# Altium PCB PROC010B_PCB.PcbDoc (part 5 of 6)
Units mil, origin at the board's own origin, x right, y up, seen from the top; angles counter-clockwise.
Board outline 3180 x 2565 mil, 6 copper layers (TOP, L2, L3, L4, L5, BOTTOM), stack 55.54 mil thick; 362 components, 264 nets, 1248 pads, 1144 vias.
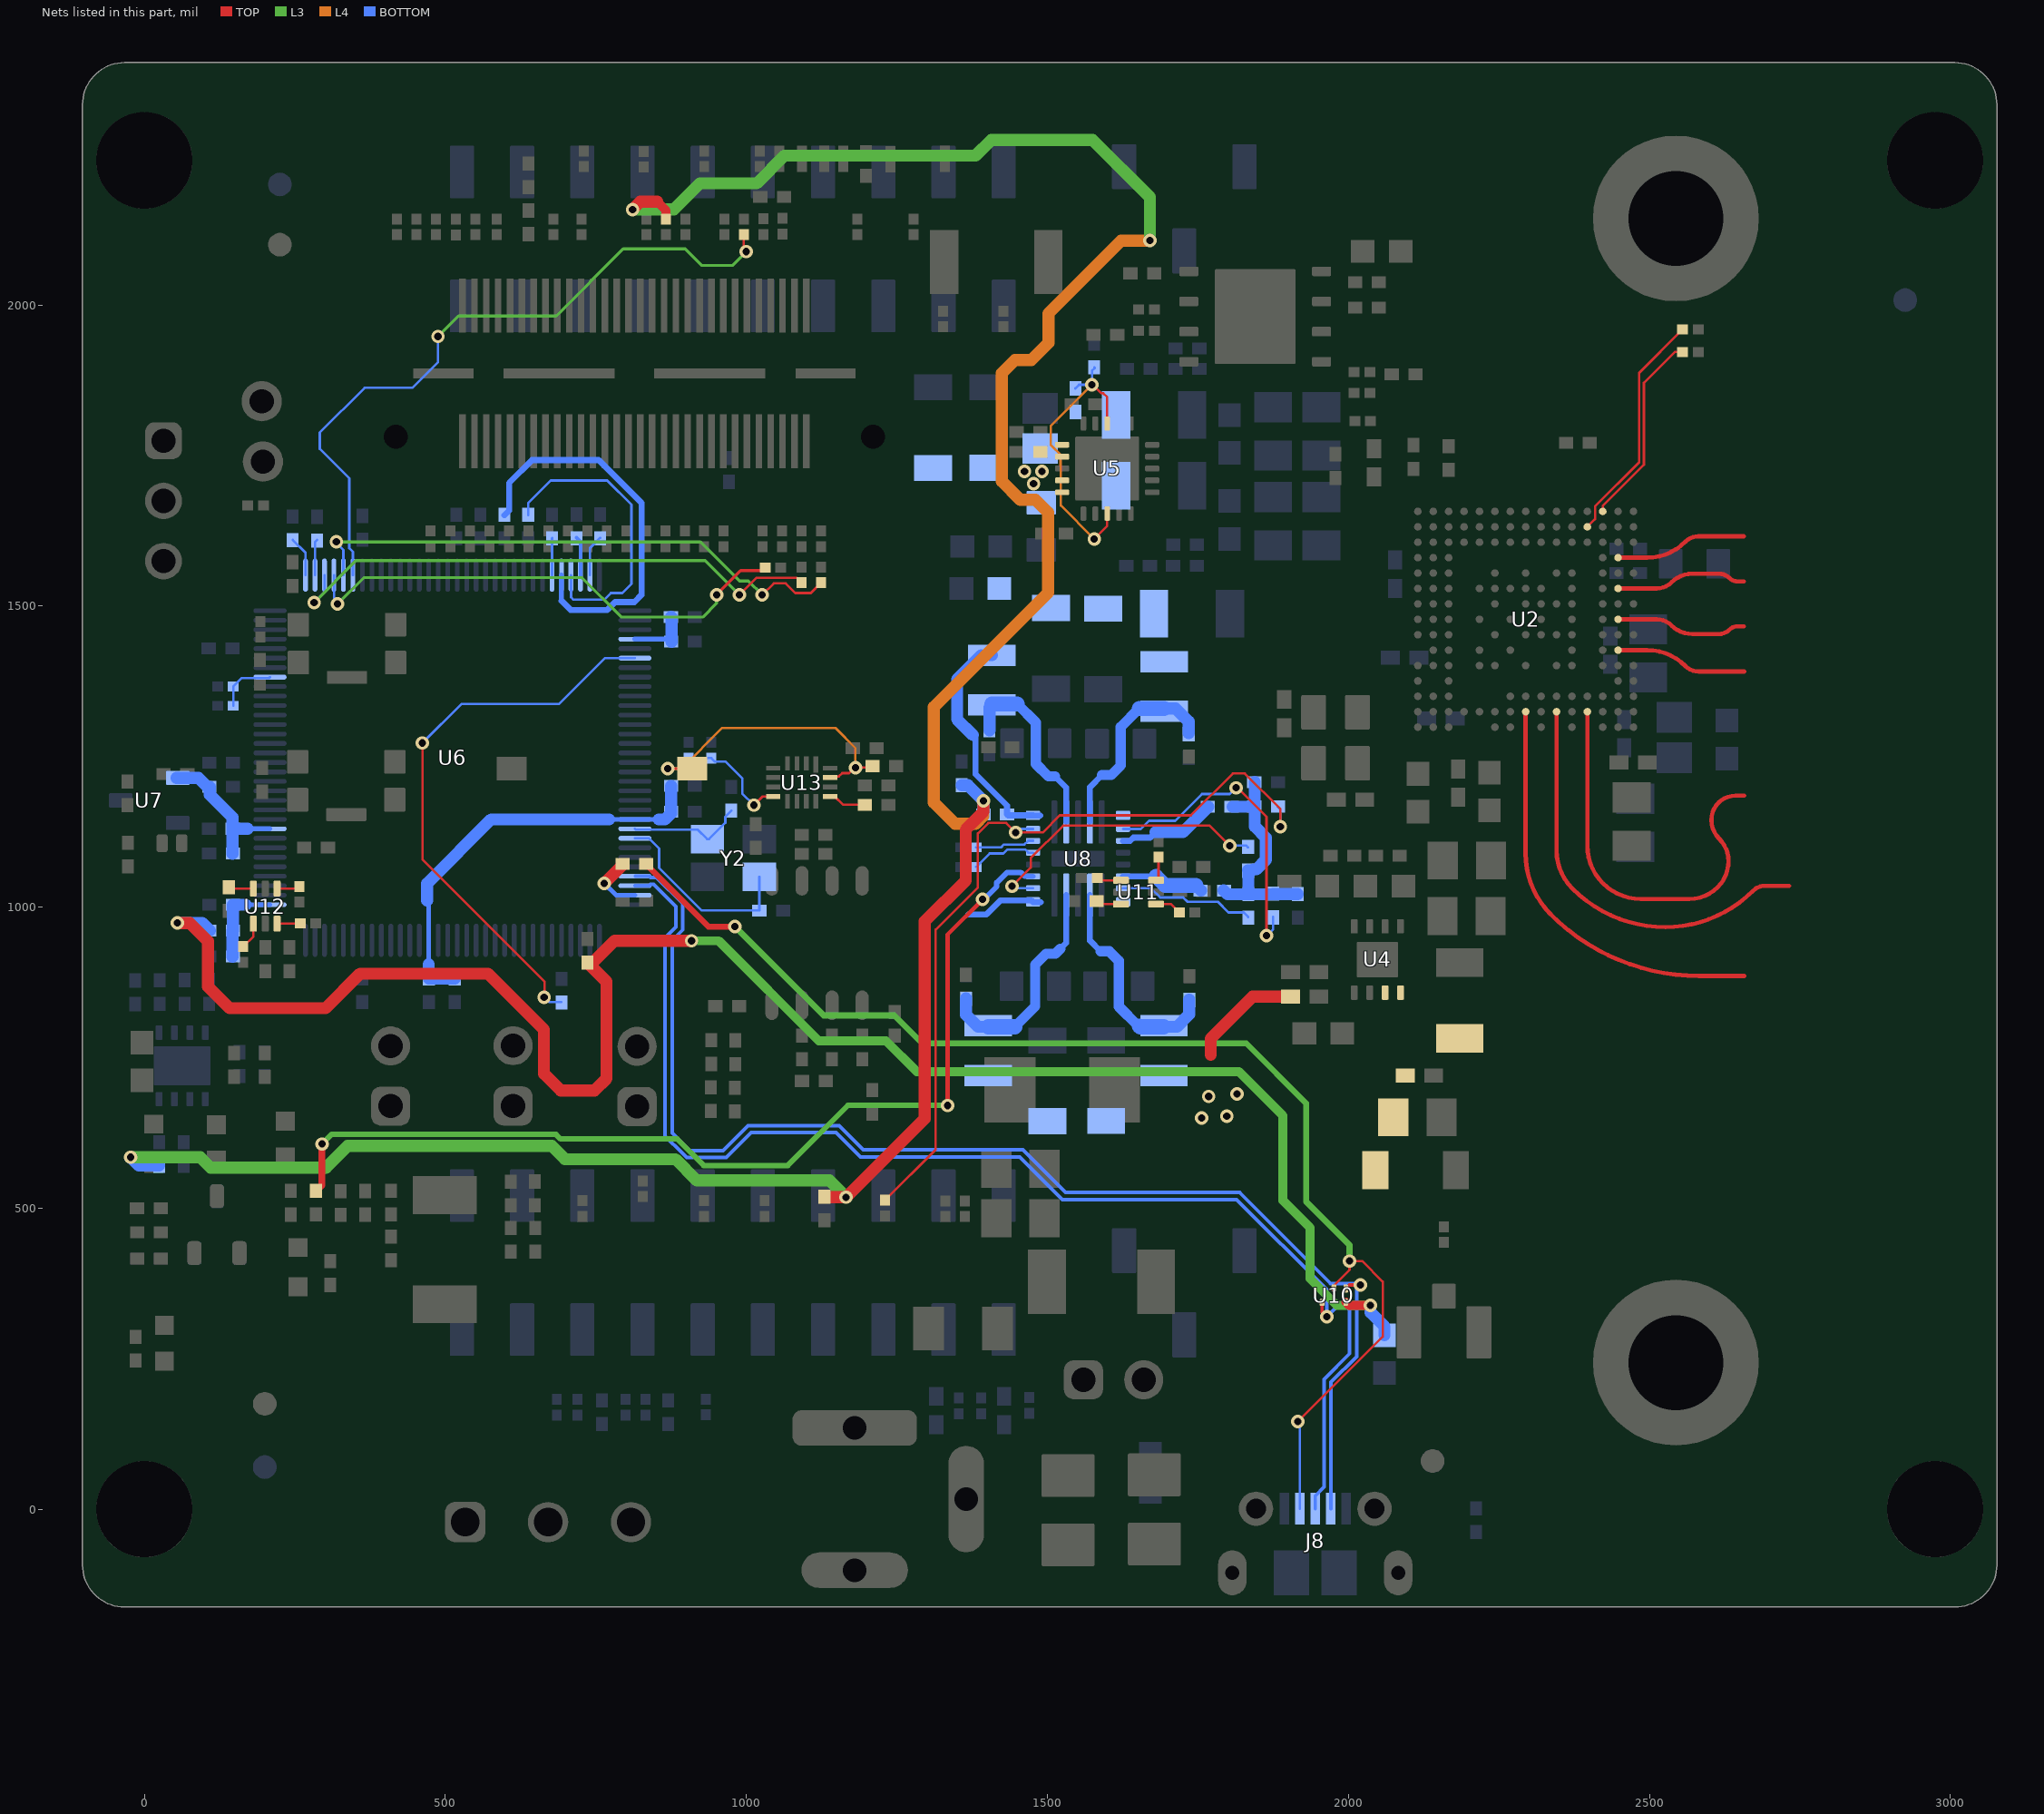
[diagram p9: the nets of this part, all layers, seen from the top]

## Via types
v1: diameter 22.4, hole 12.2, TOP to BOTTOM, tented both sides, 621 vias
v2: diameter 13.77/15.74 (per signal layer), hole 5.9, TOP to L2, tented top, 508 vias
v3: diameter 19.68, hole 7.87, TOP to BOTTOM, tented top, 7 vias
v4: diameter 19.68, hole 7.87, TOP to BOTTOM, 4 vias
v5: diameter 19.68, hole 7.87, TOP to BOTTOM, tented both sides, 3 vias
v6: diameter 19.68, hole 7.87, TOP to BOTTOM, tented bottom, 1 vias

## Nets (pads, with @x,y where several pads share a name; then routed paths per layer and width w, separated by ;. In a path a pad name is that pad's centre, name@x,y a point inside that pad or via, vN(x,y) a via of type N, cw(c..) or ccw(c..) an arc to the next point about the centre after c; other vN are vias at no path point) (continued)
NetR123_1: R123.1 U6.63 | length 69.2
  BOTTOM w4: U6.63@740.14,1551.19 740.14,1596.11 R123.1@757.28,1613.25
NetR124_1: R124.1 U6.61 | length 504.9
  BOTTOM w4: R124.1@637.72,1650.75 637.72,1671.22 675.02,1708.52 768.8,1708.52 809,1668.32 809,1536.5 794,1521.5 775,1521.5 764,1510.5 713,1510.5 709,1514.5 709,1550.83 U6.61@708.64,1551.19
NetR125_1: R125.1 S1.2 U13.15 | length 504.1
  TOP w4: v1(869.19,1230) S1.2@910,1230 ; U13.15@1139.1,1215.08 1140.97,1216.96 1153.7,1216.96 1159.2,1222.46 1170.65,1222.46 v1@1179.8,1231.61 ; v1(1181.07,1231.61) 1207.07,1231.61 R125.1@1209.58,1234.12
  L4 w4: v1(869.19,1230) 892.6,1230 960.04,1297.45 1147.8,1297.45 1181.07,1264.17 v1(1181.07,1231.61)
NetR126_1: R126.1 U6.62 | length 64.8
  BOTTOM w6: R126.1@717.68,1613.25 724.39,1606.54 U6.62@724.39,1551.19
NetR127_1: R127.1 U6.60 | length 666.9
  BOTTOM w8: 692.89,1508.61 U6.60@692.89,1551.19
  BOTTOM w10: R127.1@598.12,1650.75 606,1658.63 606,1704.43 643.95,1742.38 754.73,1742.38 825.8,1671.31 825.8,1518.3 814,1506.5 782,1506.5 769,1493.5 708,1493.5 692.89,1508.61
NetR128_2: R128.2 U6.33 | length 67.5
  BOTTOM w4: R128.2@246.5,1609.95 267.7,1588.75 U6.33@267.7,1551.19
NetR129_2: R129.2 U6.34 | length 59.9
  BOTTOM w4: U6.34@283.44,1551.19 283.44,1606.04 R129.2@287,1609.6
NetR143_1: R143.1 U8.16 | length 165
  BOTTOM w10: U8.16@1625.81,1110.02 1637.53,1110.03 1643,1115.5 1671,1115.5 1679.82,1124.32
  BOTTOM w20: 1679.82,1124.32 1725.27,1124.32 R143.1@1767.45,1166.5
NetR144_2: R144.2 U8.5 | length 108.5
  BOTTOM w4: R144.2@1381.77,1066.69 1404.08,1089 1427,1089 1433.49,1095.49 1462.92,1095.49 1468.07,1090.34 U8.5@1476.2,1090.34
NetR146_1: R146.1 U8.6 | length 98.9
  BOTTOM w4: R146.1@1381.77,1099.19 1423.19,1099.19 1427.83,1103.83 1461.94,1103.83 1468.13,1110.03 U8.6@1476.2,1110.02
NetR147_1: R147.1 U8.19 | length 139
  BOTTOM w10: U8.19@1625.81,1050.97 1680.53,1050.97
  BOTTOM w20: R147.1@1746.6,1036 R147.1@1755.1,1027.5
  BOTTOM w25: 1680.53,1050.97 1695.5,1036 R147.1@1746.6,1036
NetR152_1: R152.1 U6.95 | length 104
  TOP w20: v1(764,1039.5) 795.1,1070.6 R152.1@795.1,1071.5
  BOTTOM w8: v1(764,1039.5) 783.81,1019.69 U6.95@814.94,1019.69
NetR179_1: R179.1 U11.3 | length 43.1
  TOP w4: R179.1@1581.25,1009.92 1586.11,1005.06 U11.3@1622.33,1005.07
NetR180_2: R180.2 U11.1 | length 41.2
  TOP w4: R180.2@1582.77,1048.33 1586.66,1044.44 U11.1@1622.33,1044.44
NetR181_1: R181.1 U11.4 | length 44.4
  TOP w4: U11.4@1680.59,1005.07 1705.34,1005.06 R181.1@1719.23,991.17
NetR182_1: R182.1 U11.6 | length 40
  TOP w4: U11.6@1680.59,1044.44 1684.67,1048.52 R182.1@1684.67,1082.79
NetR184_1: R184.1 U12.3 | length 41.4
  TOP w4: R184.1@140.38,1032.25 141.96,1030.67 U12.3@181.13,1030.67
NetR185_2: R185.2 U12.1 | length 38.8
  TOP w4: U12.1@220.5,1030.67 254.29,1030.67 R185.2@257.83,1034.21
NetR186_1: R186.1 U12.6 | length 38.7
  TOP w4: U12.6@220.5,972.4 257.87,972.41 R186.1@258.79,973.33
NetR188_2: R188.2 U12.4 | length 45.4
  TOP w4: R188.2@163.83,934.21 181.12,951.5 U12.4@181.13,972.4
NetR194_2: R194.2 U6.59 | length 61.9
  BOTTOM w4: U6.59@677.14,1551.19 677.14,1612.57 R194.2@677.52,1612.95
NetR195_1: R195.1 U13.13 | length 63.2
  TOP w4: U13.13@1139.1,1183.59 1146.9,1183.59 1160.68,1169.81 R195.1@1196.58,1169.81
NetR197_2: R197.2 U2.P4 | length 393.5
  TOP w4: U2.P4@2396.91,1631.44 2409.75,1644.28 2409.75,1665.25 2483,1738.5 2483,1887.2 2555.01,1959.21 R197.2@2555.01,1959
NetR198_2: R198.2 U2.R3 | length 327.3
  TOP w4: U2.R3@2422.5,1657.03 2422.5,1666 2491,1734.5 2491,1870.64 2542.36,1922 R198.2@2555.01,1922
PGOOD: R27.1 R107.2 R138.2 R141.2 R159.1 | length 4589.2
  TOP w15: 852.15,2171.36 866.61,2156.9 R27.1@866.61,2142.71
  TOP w20: v1(811,2158.5) 823.86,2171.36 852.15,2171.36 ; R107.2@1129.75,518.18 v1(1165.78,518.18) 1296.38,648.78 1296.38,976.2 1364.54,1044.36 1364.54,1129.13 1393.72,1158.31 v1(1393.72,1176.67)
  L3 w20: v1(-23,584.5) 93.04,584.5 110.2,567.34 301.89,567.34 337.84,603.3 676.71,603.3 698.74,581.28 882.26,581.28 917.54,546 1137.96,546 v1(1165.78,518.18) ; v1(811,2158.5) 879.46,2158.5 922.83,2201.86 1017.13,2201.86 1063.27,2248 1381,2248 1407,2274 1575.14,2274 1670.34,2178.8 v1(1670.34,2106.77)
  L4 w20: v1(1393.72,1176.67) 1393.72,1150.96 1381.05,1138.3 1346.64,1138.3 1311.35,1173.59 1311.35,1332.35 1501.24,1522.24 1501.24,1655.5 1480.29,1676.45 1454.85,1676.45 1424.36,1706.93 1424.36,1886.63 1446.28,1908.55 1473.25,1908.55 1501.76,1937.06 1501.76,1985.85 1622.68,2106.77 v1(1670.34,2106.77)
  BOTTOM w20: v1(-23,584.5) -9.31,570.81 R159.1@24.43,570.81 ; R138.2@1357.78,1202.28 1368.11,1202.28 v1(1393.72,1176.67) R141.2@1393.72,1154.01
PMIC_1V0: C30.2 C31.2 C32.2 C40.2 C81.2 L4.2 L5.1 L8.1 R46.1 R120.2 U5.1 U5.2 U5.4 U5.5 U8.1 | length 130.9
  BOTTOM w10: 1368.72,987.88 1398.93,987.88 1422.37,1011.32 1473.53,1011.32 U8.1@1476.2,1008.65 ; U8.1@1476.2,1007.88 1488.82,1007.88
  other v1: 1477.07,1703.31 1461.98,1723.32 1491.25,1723.21
PMIC_1V2: C54.2 L1.2 L9.1 U8.14
PMIC_1V8: C21.1 C23.1 C25.1 C82.2 L3.2 L7.1 R84.2 U4.7 U4.8 U8.21 | length 188.3
  TOP w20: 1771.28,754.5 1771.28,781.5 1841,851.22 R84.2@1903.73,851.22
  other v1: 1756,649.5 1798,652.5 1768,685.5 1815,689.5
PMIC_CLK: R97.2 U8.3 | length 1666.1
  TOP w7.08: v1(1334.3,670.49) 1334.3,954.63 v1(1392.53,1012.86)
  TOP w11: R97.2@285,528.05 295,538.05 v1(295,606.5)
  L3 w9: v1(295,606.5) 310.78,622.28 683.9,622.28 691.42,614.75 885.25,614.75 929.05,570.95 1068.95,570.95 1168.49,670.49 v1(1334.3,670.49)
  BOTTOM w9: v1(1392.53,1012.86) 1394.86,1012.86 1416,1034 1416,1040.48 1433.11,1057.59 1455.85,1057.59 1462.47,1050.97 U8.3@1476.2,1050.97
PMIC_EN1: R102.2 R142.1 U8.7 | length 1350.2
  TOP w4: R102.2@1230.25,513.27 1314.37,597.39 1314.37,962.49 1384.59,1032.71 1384.59,1122.31 1401.99,1139.71 1431.79,1139.71 v1(1447.5,1124) 1492.41,1124 1520.75,1152.33 1738.33,1152.33 1808,1222 1828,1222 1887,1163 v1(1887,1133.5)
  BOTTOM w4: v1(1447.5,1124) 1453.21,1129.71 U8.7@1476.2,1129.71 ; R142.1@1882.25,1167.04 1887,1162.29 v1(1887,1133.5)
PMIC_EN2: R148.1 U8.15 | length 520.5
  TOP w4: v1(1813.65,1198) 1816,1198 1864,1150 v1(1864,952.5)
  BOTTOM w4: U8.15@1625.81,1129.71 1655.21,1129.71 1668.82,1143.32 1712.32,1143.32 1756.81,1187.81 1802.78,1187.81 1813.65,1198.69 v1(1813.65,1198) ; v1(1864,952.5) 1875,963.5 R148.1@1875,983.6
PMIC_EN3: R145.1 U8.2 | length 494.2
  TOP w4: v1(1441.5,1034.5) 1472.48,1065.48 1472.48,1081.57 1526.25,1135.33 1769.67,1135.33 v1(1803,1102)
  BOTTOM w4: v1(1441.5,1034.5) 1444.71,1031.29 U8.2@1476.2,1031.28 ; v1(1803,1102) 1830.49,1102 R145.1@1833.44,1099.05
PMIC_NRST: R150.2 U8.20 | length 227.8
  BOTTOM w4: U8.20@1625.81,1031.28 1672.21,1031.29 1687.5,1016 1725.5,1016 1732.5,1009 1782.99,1009 1800.99,991 1825.99,991 R150.2@1833.74,983.25
PMICOUT_3V3: C55.2 L2.2 R133.1 R141.1 U8.8 | length 388.9
  BOTTOM w10: 1376.47,1285.53 1380.65,1281.35 1380.65,1220.85 1433.09,1168.41 R141.1@1433.09,1154.01 1434.74,1152.35 U8.8@1476.2,1152.35 ; U8.8@1476.2,1152.15 1488.2,1152.15
  BOTTOM w20: 1376.47,1285.53 1350,1312 1350,1378.33 1389.91,1418.24 L2.2@1407.85,1418.24
PMICVIO_3V3: R139.2 R142.2 R143.2 R145.2 R147.2 R148.2 R149.1 R150.1 | length 376.5
  BOTTOM w20: R147.2@1792.9,1027.5 1799.35,1021.05 R150.1@1833.74,1021.05 ; R143.2@1807.91,1166.5 R142.2@1844.45,1167.04 ; R139.2@1844.45,1207.54 R142.2@1844.45,1167.04 ; R149.1@1916.14,1021.05 1915.79,1021.4 1875,1021.4 1874.65,1021.05 R150.1@1833.74,1021.05 ; R150.1@1833.74,1021.05 1833.74,1060.95 1833.44,1061.25 1840.75,1061.25 1842,1062.5 1847,1062.5 1863,1078.5 1863,1115 1844.45,1133.55 R142.2@1844.45,1167.04
RX1: U2.M2 | length 218.6
  TOP w7.08: U2.M2@2448.09,1580.26 2496.4,1580.26 ccw(c2496.4,1669.28) 2559.79,1606.78 cw(c2581.07,1585.5) 2581.07,1615.6 2657.22,1615.6
RX2: U2.K2 | length 218.8
  TOP w7.08: U2.K2@2448.09,1529.08 2512.28,1529.08 ccw(c2512.28,1563.6) 2536.69,1539.19 cw(c2571.24,1504.66) 2571.24,1553.5 2615.82,1553.5 cw(c2615.82,1528.95) 2633.18,1546.31 ccw(c2646.47,1559.58) 2646.47,1540.8 2656.92,1540.8
RX3: U2.H2 | length 218.8
  TOP w7.08: U2.H2@2448.09,1477.9 2512.28,1477.9 cw(c2512.28,1443.38) 2536.69,1467.79 ccw(c2571.24,1502.32) 2571.24,1453.48 2615.82,1453.48 ccw(c2615.82,1478.03) 2633.18,1460.67 ; 2633.19,1460.68 cw(c2646.47,1447.4) 2646.47,1466.18 2656.92,1466.18
RX4: U2.F2 | length 218.9
  TOP w7.08: U2.F2@2448.09,1426.72 2496.4,1426.72 cw(c2496.4,1337.7) 2559.79,1400.2 ccw(c2581.5,1421.91) 2581.5,1391.2 2657.4,1391.2
SPICLK1: R75.1 R76.1 U13.8 | length 193.5
  TOP w4: v1(1012.58,1169.33) 1026.83,1183.59 U13.8@1044.61,1183.59
  BOTTOM w4: R75.1@904.07,1247.48 R76.1@941.93,1247.48 947.94,1241.48 965.54,1241.48 993.15,1213.86 993.15,1188.75 v1(1012.58,1169.33)
SS_CTRL: R119.2 R120.1 U5.8 U5.18 | length 504.4
  TOP w4: v1(1574.07,1867.4) 1575.74,1867.4 1589.91,1853.24 1592.9,1853.24 1599.35,1846.8 U5.18@1599.35,1803.12 ; v1(1577.96,1611.47) 1599.35,1632.86 U5.8@1599.35,1653.52
  L4 w4: v1(1574.07,1867.4) 1505.5,1798.83 1505.5,1767.57 1521.82,1751.25 1521.82,1731.91 1522.36,1731.91 1522.36,1667.08 v1(1577.96,1611.47)
  BOTTOM w4: R120.1@1546.63,1861.48 1552.56,1867.4 v1(1574.07,1867.4) 1574.07,1890.75 1578.87,1895.55 R119.2@1577.96,1896.45
SW0: L2.1 R190.2 U8.10 | length 322.3
  BOTTOM w10: 1512.51,1217 1531.31,1198.2 U8.10@1531.32,1141.13
  BOTTOM w17: 1449.82,1337.53 1480.85,1306.5 1480.85,1237.8 1501.65,1217 1512.51,1217
  BOTTOM w20: R190.2@1403.85,1293.43 1403.85,1331.56 L2.1@1407.85,1335.56
  BOTTOM w25: L2.1@1407.85,1337.53 1449.82,1337.53
SW1: L1.1 R191.2 U8.12 | length 342.4
  BOTTOM w10: U8.12@1570.69,1141.13 1570.69,1199.24 1590.95,1219.5
  BOTTOM w17: 1590.95,1219.5 1606.05,1219.5 1621.95,1235.4 1621.95,1299.23 1652.68,1329.96
  BOTTOM w20: L1.1@1694.05,1329.96 1713.07,1329.96 1734.8,1308.23 R191.2@1734.8,1288.55
  BOTTOM w25: 1652.68,1329.96 L1.1@1694.05,1329.96
SW2: L4.1 R192.2 U8.25 | length 379.6
  BOTTOM w10: 1521.55,930.8 1531.31,940.56 U8.25@1531.32,1019.87
  BOTTOM w17: 1445.92,801.17 1479.85,835.1 1479.85,904.34 1498.01,922.5 1513.25,922.5 1521.55,930.8
  BOTTOM w20: R192.2@1364.9,848.45 1364.9,821.17 1384.9,801.17 L4.1@1401.55,801.17
  BOTTOM w25: L4.1@1401.55,801.17 1445.92,801.17
SW3: L3.1 R193.2 U8.23 | length 377.5
  BOTTOM w10: U8.23@1570.69,1019.87 1570.69,944.32 1588.51,926.5
  BOTTOM w17: 1588.51,926.5 1602.85,926.5 1618.65,910.7 1618.65,834.7 1650.84,802.51 1652.68,802.51
  BOTTOM w20: L3.1@1693.55,801.17 1714.99,801.17 1735.6,821.78 R193.2@1735.6,846.45
  BOTTOM w25: 1652.68,802.51 1654.02,801.17 L3.1@1693.55,801.17
TX1: U2.B4 | length 696.2
  TOP w7.08: U2.B4@2396.91,1324.36 2396.91,1102.05 ccw(c2485.46,1102.05) 2485.46,1013.5 2566.65,1013.5 ccw(c2566.65,1079.79) 2613.53,1032.92 ; 2613.54,1032.93 ccw(c2570.24,1076.22) 2631.47,1076.22 ccw(c2578.8,1076.22) 2616.05,1113.46 cw(c2647.37,1144.78) 2603.07,1144.78 cw(c2643.55,1144.8) 2614.93,1173.43 cw(c2642.62,1145.76) 2642.61,1184.9 2657.3,1184.9
TX2: U2.B6 | length 696.2
  TOP w7.08: U2.B6@2345.73,1324.36 2345.73,1094.33 ccw(c2435.71,1094.33) 2372.08,1030.71 ccw(c2526.5,1185.06) 2526.5,966.73 ccw(c2526.5,1172.53) 2672,1026.99 cw(c2692.07,1006.94) 2692.06,1035.3 2732.11,1035.3
TX3: U2.B8 | length 696.3
  TOP w7.08: U2.B8@2294.55,1324.36 2294.34,1324.15 2294.34,1089.06 ccw(c2437.96,1089.06) 2336.4,987.51 ccw(c2582.22,1233.3) 2582.22,885.68 2657.3,885.68
VBUS_1_DETECT: C69.2 R151.1 R153.2 U6.1 | length 147.8
  BOTTOM w8: 168.55,1003.95 U6.1@208.64,1003.95
  BOTTOM w20: R153.2@146.55,917.74 146.55,961.04 146.95,961.44 146.95,1003.56 147.34,1003.95 168.55,1003.95
VDDC_1: C62.2 C64.2 C74.2 C75.2 U6.87 U6.115 | length 701
  BOTTOM w8: 469.65,1010.85 472.42,1008.08 472.42,905.08 ; 771.82,1145.68 854.18,1145.68
  BOTTOM w20: 469.65,1010.85 469.65,1039.15 576.18,1145.68 771.82,1145.68 ; 472.42,905.08 472.42,881.71 472.68,881.45 C74.2@515.6,881.45 ; 854.18,1145.68 865,1145.68 874.96,1155.64 C64.2@874.96,1158.3 C62.2@874.96,1201.2
XDSET_1_D_N: J8.2 U6.93 U10.1 | length 2188.8
  TOP w6: U10.1@1995.68,366.33 2001.88,372.52 v1(2019.99,372.52)
  BOTTOM w6: U6.93@815.54,1051.19 838.99,1051.19 840.8,1049.38 850.87,1049.38 894.6,1005.65 894.6,962.25 876.6,944.24 876.6,624.75 905.6,595.75 905.6,595.5 961.6,595.5 1003.1,637 1153.9,637 1194.2,596.7 1459.1,596.7 1529.89,525.91 1819.18,525.91 1970.6,374.5 2019.6,374.5 2020.6,373.5 2013.6,366.5 2013.6,335.81 2013.6,253.5 1971.19,211.09 1971.19,32.06 J8.2@1971.19,0.88
XDSET_1_D_P: J8.3 U6.94 U10.4 | length 2188.5
  TOP w6: U10.4@1956.31,343.69 1956.31,327.19 v1(1964,319.5)
  BOTTOM w6: U6.94@814.94,1035.44 838.69,1035.44 841.03,1037.78 846.07,1037.78 883,1000.85 883,967.05 865,949.05 865,619.94 894,590.94 894,590.7 900.79,583.9 966.4,583.9 1007.9,625.4 1149.1,625.4 1189.4,585.1 1454.3,585.1 1525.09,514.31 1814.38,514.31 1964,364.69 v1(1964,319.5) 1984.5,340 1993,340 2002,331 2002,258.31 1959.59,215.9 1959.59,36.86 1945,22.27 J8.3@1945,0.88
XDSET_1_ID: J8.4 R152.2 U10.2 | length 2115.1
  TOP w4: v1(1916,145.5) 2057.04,286.54 2057.04,377.81 2022.74,412.11 v1(2001.89,412.11) 2001.89,397.39 1976,371.5 U10.2@1976,367.31
  TOP w10: R152.2@832.9,1071.5 936.9,967.5 v1(981,967.5)
  L3 w10: v1(981,967.5) 1128.41,820.09 1245.8,820.09 1292.12,773.77 1830.37,773.77 1929.79,674.35 1929.79,510.85 2001.89,438.76 v1(2001.89,412.11)
  BOTTOM w4: v1(1916,145.5) 1919.41,142.09 J8.4@1919.41,0.88
XDSET_1_VBUS: R151.2 R154.2 R161.2 U10.6 | length 3036.4
  TOP w15: U10.6@1995.68,343.69 2000.79,338.59 v1(2036.61,338.59)
  TOP w20: v1(55,973.5) 75.54,973.5 105.77,943.27 105.77,867.8 141.57,832 301,832 358.51,889.51 570.49,889.51 663.79,796.21 663.79,722.96 691.59,695.16 747.69,695.16 767.67,715.14 767.67,876.15 R154.2@736,907.81 744.88,907.81 781.07,944 v1(909,944)
  L3 w15: v1(909,944) 954.04,944 1120.15,777.89 1231.87,777.89 1282.88,726.87 1818.03,726.87 1891.09,653.81 1891.09,512.9 1936.34,467.65 1936.34,383.2 1980.95,338.59 v1(2036.61,338.59)
  BOTTOM w20: v1(55,973.5) 96.29,973.5 R151.2@108.75,961.04 ; v1(2036.61,338.59) 2036.61,326.66 2060,303.26 R161.2@2060,289
XDSET_LOGGER: R135.2 R136.2 U6.25 | length 99.3
  BOTTOM w4: R136.2@147.77,1334.29 R135.2@147.77,1366.19 162.08,1380.5 207.24,1380.5 U6.25@208.64,1381.9
XDSET_NRST: R155.1 U6.70 | length 951
  TOP w4: v1(462,1272.5) 462,1079.01 665,876.01 665,850 v1(664,850)
  BOTTOM w4: v1(462,1272.5) 527,1337.5 689.05,1337.5 765.05,1413.5 814.83,1413.5 U6.70@814.94,1413.39 ; v1(664,850) 665,850 672.75,842.25 R155.1@692.78,842.25
XDSET_OSC0: C70.2 U6.88 Y2.1 | length 192.6
  BOTTOM w4: U6.88@814.94,1129.93 816.37,1128.5 919.49,1128.5 Y2.1@935,1112.99 937.99,1112.99 965,1140 965,1150.16 C70.2@975,1160.16
XDSET_OSC1: C63.2 U6.89 Y2.3 | length 330.9
  BOTTOM w4: U6.89@814.94,1114.18 838.17,1114.18 855,1097.35 855,1065 925.64,994.36 C63.2@1021.61,994.36 Y2.3@1021.61,1050
XDSET_TCK: R70.2 U6.35 | length 929.6
  TOP w4: v1(988.42,1518.55) 1016.78,1546.91 1083.15,1546.91 R70.2@1091.33,1538.73
  L3 w5: v1(282,1505.5) 351.71,1575.21 931.76,1575.21 v1(988.42,1518.55)
  BOTTOM w4: v1(282,1505.5) 299.19,1522.69 U6.35@299.19,1551.19
XDSET_TDI: R30.2 U6.38 | length 1170.3
  TOP w4: R30.2@995.75,2116.73 995.75,2093.75 1000,2089.5 v1(1000,2088.5)
  L3 w5: v1(487.75,1947.66) 521.88,1981.78 684.05,1981.78 795.46,2093.2 898.29,2093.2 926.04,2065.45 976.95,2065.45 v1(1000,2088.5)
  BOTTOM w4: U6.38@346.44,1551.19 346.44,1590.07 340.54,1595.97 340.54,1711.96 291.56,1760.94 291.56,1788.05 365.97,1862.46 444.96,1862.46 487.75,1905.25 v1(487.75,1947.66)
XDSET_TDO: R71.2 U6.37 | length 923.6
  TOP w4: v1(1026.32,1518.55) 1045.4,1537.64 1065.2,1537.64 1081.32,1521.51 1107.12,1521.51 R71.2@1124.33,1538.73
  L3 w5: v1(319,1606.5) 923.66,1606.5 988.55,1541.61 1003.26,1541.61 v1(1026.32,1518.55)
  BOTTOM w4: v1(319,1606.5) 319,1604.5 330.69,1592.81 U6.37@330.69,1551.19
XDSET_TMS: R69.2 U6.36 | length 847.8
  TOP w5: v1(950.52,1518.55) 990.59,1558.62 1026.11,1558.62 R69.2@1031.11,1563.62
  L3 w5: v1(321,1503.5) 364.66,1547.16 726.88,1547.16 792.54,1481.5 927.47,1481.5 950.52,1504.55 v1(950.52,1518.55)
  BOTTOM w4: U6.36@314.94,1551.19 314.94,1509.56 v1(321,1503.5)
XDSET_VBAT: C49.2 R134.1 U6.68 | length 104.2
  BOTTOM w8: U6.68@814.94,1444.89 871.46,1444.89 R134.1@875.75,1440.6
  BOTTOM w20: C49.2@875.05,1481.9 875.75,1481.2 R134.1@875.75,1440.6
XDSET_VREFA: C66.2 C67.2 R140.1 U6.9 U7.1 | length 250.2
  BOTTOM w8: 171.57,1129.93 U6.9@208.64,1129.93
  BOTTOM w20: U7.1@53.36,1214.49 89.72,1214.49 104.69,1199.52 108.75,1199.52 108.75,1186.75 146.49,1149.01 C66.2@146.49,1130.1 ; C67.2@146.55,1088.8 146.49,1088.86 C66.2@146.49,1130.1 ; 171.57,1129.93 146.66,1129.93 C66.2@146.49,1130.1
pads on no net: FID1.1 FID2.1 FID3.1 FID4.1 FID5.1 FID6.1 FID7.1 J1.15 J1.17 J1.19 J1.21 J1.23 J1.25 J1.27 J1.29 J1.31 J1.33 J1.35 J1.37 J1.39 J1.41 J1.43 J1.45 J1.47 J1.49 J1.MH1 J1.MH2 J5.3 J5.11 J6.4 J6.7 J6.20 J8.7 J8.8 LBL1.0 SW1.1 SW1.3 SW2.1 SW2.3 U1. U2.B15 U2.D1 U5.9 U5.17 U5.21@1571.99,1700.96 U5.21@1571.99,1755.68 U5.21@1626.71,1700.96 U5.21@1626.71,1755.68 U6.2 U6.3 U6.4 U6.5 U6.6 U6.11 U6.12 U6.13 U6.14 U6.15 U6.18 U6.19 U6.20 U6.21 U6.22 U6.23 U6.24 U6.27 U6.29 U6.30 U6.31 U6.32 U6.41 U6.42 U6.43 U6.44 U6.45 U6.46 U6.49 U6.50 U6.53 U6.54 U6.56 U6.57 U6.65 U6.67 U6.71 U6.72 U6.73 U6.74 U6.75 U6.76 U6.77 U6.78 U6.81 U6.82 U6.83 U6.84 U6.85 U6.86 U6.91 U6.92 U6.97 U6.98 U6.99 U6.100 U6.102 U6.103 U6.104 U6.105 U6.106 U6.107 U6.108 U6.109 U6.110 U6.111 U6.112 U6.116 U6.117 U6.118 U6.119 U6.120 U6.121 U6.123 U6.124 U6.125 U6.126 U6.127 U6.128 U7.3 U8. U9.7 U9.9@38.03,736.32 U9.9@87.64,736.32 U13.9 U13.12

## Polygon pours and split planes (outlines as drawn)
no net on Top Solder (solid, pour order 1226): 1710.23,1993.88 1762.33,1993.88 1762.33,2017.48 1710.23,2017.48 1710.23,1993.88
no net on Top Solder (solid, pour order 1228): 1710.23,2043.88 1762.33,2043.88 1762.33,2067.48 1710.23,2067.48 1710.23,2043.88
no net on Top Solder "Top Solder-No Net" (solid, pour order 1234): 69 vertices, not listed, extent 2260,825.7 3047,1773.5
no net on Top Solder (solid, pour order 1233): 1596,2324.5 1596,2219.5 1974,2219.5 1974,2146.5 2358,2146.5 2358,2324.5 1596,2324.5
no net on Bottom Solder "Bottom Solder-No Net" (solid, pour order 1235): 3068.95,-131.45 2330.5,-131.45 2330.48,-131.48 2318.95,-131.48 2318.95,618.55 3068.95,618.55 3068.95,-131.45
no net on Bottom Solder (solid): 43 vertices, not listed, extent 1991,-132.5 3047,2365
AR_1P3_RF2 on TOP "GND 1-No Net" (solid, remove dead copper, pour order 1254): 1657.89,1682.73 1657.89,1713.42 1663.59,1719.12 1690.73,1719.12 1695.53,1714.32 1695.53,1678.14 1689.72,1672.34 1668.28,1672.34
AR_1P3_RF1 on TOP "GND 1-No Net" (solid, remove dead copper, pour order 1252): 1785.39,1652.08 1833.48,1700.17 1833.48,1791.4 1790.17,1834.71 1716.34,1834.71 1658.82,1777.19 1658.82,1744.08 1664.23,1738.67 1689.96,1738.67 1706.01,1722.61 1706.01,1632.47 1727,1611.48 1744.79,1611.48
PMIC_1V0 on TOP "GND 1-No Net" (solid, remove dead copper, pour order 1250): 1450.36,1705.57 1479.75,1676.17 1534.9,1676.18 1542.33,1683.6 1542.33,1768.21 1535.03,1775.51 1478.9,1775.51 1450.36,1746.97
GND on TOP "TOP-GND 1" (solid, remove dead copper, pour order 1179): 2395.5,94 2694.5,94 2694.5,396 2395.5,396 2395.5,94
GND on TOP "TOP-GND 12" (solid, remove dead copper, pour order 1172): 32 vertices, not listed, extent 1348,789 1754,923
GND on TOP "TOP-GND 11" (solid, remove dead copper, pour order 1170): 18 vertices, not listed, extent 1429,1204 1749.46,1305.1
GND on TOP "TOP-GND 10" (solid, remove dead copper, pour order 1145): 1644.54,995.52 1644.54,1019.98 1622,1019.98 1622,1029.52 1644.54,1029.52 1644.54,1057 1658.38,1057 1658.38,1039.67 1658.37,1039.67 1658.37,995.52 1644.54,995.52
GND on TOP "TOP-GND 7" (solid, remove dead copper, pour order 1180): 1414,86.5 1414,48.5 1486,-23.5 1724,-23.5 1726,-25.5 1726,-89.5 1692,-123.5 1116,-123.5 1091,-98.5 1091,14.5 1108,31.5 1270,31.5 1347.48,108.98 1391.52,108.98
GND on TOP "TOP-GND 4" (solid, remove dead copper, pour order 1162): 34 vertices, not listed, extent 2653.04,1286.86 2946.35,1345.92
GND on TOP "TOP-GND 3" (solid, remove dead copper, pour order 1163): 34 vertices, not listed, extent 2653.04,1660.87 2946.35,1719.93
RX1 on TOP "TOP-RX1" (solid, remove dead copper, pour order 1161): 34 vertices, not listed, extent 2653.04,1586.07 2946.35,1645.13
RX2 on TOP "TOP-RX2" (solid, remove dead copper, pour order 1155): 34 vertices, not listed, extent 2653.04,1511.27 2946.35,1570.32
RX3 on TOP "TOP-RX3" (solid, remove dead copper, pour order 1158): 34 vertices, not listed, extent 2653.04,1436.47 2946.35,1495.52
RX4 on TOP "TOP-RX4" (solid, remove dead copper, pour order 1159): 34 vertices, not listed, extent 2653.04,1361.66 2946.35,1420.72
TX1 on TOP "TOP-TX1" (solid, remove dead copper, pour order 1160): 34 vertices, not listed, extent 2653.04,1155.37 2946.35,1214.43
TX2 on TOP "TOP-TX2" (solid, remove dead copper, pour order 1156): 34 vertices, not listed, extent 2727.85,1005.77 3021.15,1064.82
TX3 on TOP "TOP-TX3" (solid, remove dead copper, pour order 1157): 34 vertices, not listed, extent 2653.04,856.16 2946.35,915.21
5V_IN on TOP "TOP-5V_IN 2" (solid, remove dead copper, pour order 1173): 1465,231 1465,600.33 1533.41,600.33 1533.41,352.09 1580,305.5 1603,282.5 1603,173.5 1602.5,173 1523,173
5V_IN on TOP "TOP-5V_IN 1" (solid, remove dead copper, pour order 1174): 409,328.5 438,357.5 647,357.5 667,337.5 667,187.5 653,173.5 430,173.5 409,194.5 409,328.5
5V_IN on TOP "TOP-5V_IN" (solid, remove dead copper, pour order 1169): 1617,2184 1598.5,2202.5 1512.78,2202.5 1469.96,2159.68 1469.96,2025.46 1486.92,2008.5 1545.11,2008.5 1617,2080.38
AR_1V8 on TOP "TOP-AR_1V8" (solid, remove dead copper, pour order 1168): 22 vertices, not listed, extent 2054,880 2230,1123
AR_VOUT_PA on TOP "TOP-AR_VOUT_PA" (solid, remove dead copper, pour order 1164): 17 vertices, not listed, extent 2434,1152.5 2546,1331.48
NetJ1_1 on TOP "TOP-UNNAMED_6_QSH03001XD_I1_1" (solid, remove dead copper, pour order 1175): 29 vertices, not listed, extent 1074.64,1728.5 1352,2133.5
MCU_5V on TOP "TOP-MCU_5V" (solid, remove dead copper, pour order 1166): 444,535.5 417,562.5 417,594.5 432,609.5 576,609.5 588,597.5 588,569.5 553,534.5 553,506.5 552,505.5 445,505.5 444,506.5 444,535.5
GND on TOP "GND 1-No Net" (solid, remove dead copper, pour order 1154): 1222.3,1210.76 1222.3,1158.69 1223.78,1157.21 1256.62,1157.21 1272.75,1173.35 1272.75,1211.41 1266.28,1217.88 1229.42,1217.88
5V_UNREG on TOP "TOP-5V_UNREG" (solid, remove dead copper, pour order 1171): 1645.66,428.88 1666.78,450 1760,450 1765,445 1765,177 1627,177 1627,282 1645.66,300.66
NetC26_1 on TOP "TOP-UNNAMED_9_CAPPOLARIZED_I74_1" (solid, remove dead copper, pour order 1178): 36 vertices, not listed, extent 1368.3,20.3 1735.5,757
GND on TOP "TOP-GND 6" (solid, remove dead copper, pour order 1167): 1673.76,615.01 1695,636.25 1695,676 1694.5,676.5 1694.5,735.5 1670,760 1576.63,760 1555.01,738.38 1555.01,642.99 1582.99,615.01
AR_1V2 on TOP "GND 1-No Net" (solid, remove dead copper, pour order 1165): 2344.78,1819.06 2370.22,1819.06 2379.16,1810.12 2379.16,1703.66 2355.11,1679.62 2355.11,1648.99 2351.76,1645.64 2341.19,1645.64 2337.64,1649.19 2337.64,1664.71 2318.55,1683.8 2318.55,1792.83
GND on TOP "TOP-GND" (solid, remove dead copper, pour order 1181): 2358,2324.5 2358,2146.5 1974,2146.5 1974,2219.5 1596,2219.5 1596,2324.5 2358,2324.5
NetF1_2 on TOP "TOP-UNNAMED_9_FUSE_I161_1" (solid, remove dead copper, pour order 1176): 92 vertices, not listed, extent 1062.23,96.19 1335.51,337.5
AR_1V2 on TOP "GND 1-No Net" (solid, remove dead copper, pour order 1244): 2043.97,1686.48 1972.44,1686.48 1963.98,1694.94 1963.98,1729.6 1971.63,1737.26 2053.7,1737.26 2058.49,1732.46 2058.49,1701.01
PMIC_1V8 on TOP "TOP-PMIC_2V3" (solid, remove dead copper, pour order 1177): 2224.8,870.55 2242.73,852.62 2242.73,763.68 2234.05,755 2129.43,755 2111.4,736.97 2111.4,522.48 2095.52,506.59 1742,506.59 1742,760.5 2019.66,760.5 2048.41,789.24 2048.41,860.76 2058.2,870.55
GND on TOP "TOP-GND 8" (solid, remove dead copper, pour order 1182): 996 vertices, not listed, extent 2124.85,-132.5 3047,1773.7
AR_1V2 on BOTTOM "GND 1-No Net" (solid, remove dead copper, pour order 1256): 1746.43,1467.51 1767.36,1446.57 1829.15,1446.57 1835.75,1453.17 1835.75,1529.07 1802.53,1562.29 1770.65,1562.29 1752.19,1543.57 1746.43,1537.8
GND on BOTTOM "BOTTOM-GND 8" (solid, remove dead copper, pour order 1224): 352 vertices, not listed, extent 1776.02,-130 3047.25,2366
AR_1P3_RF2 on BOTTOM "BOTTOM-AR_1P3_RF2" (solid, remove dead copper, pour order 1222): 47 vertices, not listed, extent 1708.12,1288.88 2802.34,1984.69
PMIC_1V2 on BOTTOM "GND 1-No Net" (solid, remove dead copper, pour order 1215): 25 vertices, not listed, extent 1553.42,1137.52 1856.66,1527.27
GND on BOTTOM "BOTTOM-GND 2" (solid, remove dead copper, pour order 1206): 1274.3,1801.29 1518.28,1801.29 1520.83,1803.84 1520.83,1861.25 1489.51,1892.57 1452.93,1892.57 1438.72,1906.78 1276.57,1906.78 1262,1892.22 1262,1813.59
5V_UNREG on BOTTOM "BOTTOM-5V_UNREG 3" (solid, remove dead copper, pour order 1201): 17 vertices, not listed, extent 1422,1105 1516.55,1312.76
GND on BOTTOM "BOTTOM-GND 6" (solid, remove dead copper, pour order 1212): 75 vertices, not listed, extent 1466.05,1105 1634.15,1383.5
GND on BOTTOM "BOTTOM-GND 5" (solid, remove dead copper, pour order 1211): 38 vertices, not listed, extent 1464.95,756.8 1631.55,1055.8
GND on BOTTOM "BOTTOM-GND 4" (solid, remove dead copper, pour order 1213): 1784.53,1796.5 1783.56,1797.48 1783.55,1847.73 1779.06,1852.22 1779.06,1910.56 1795,1926.5 1984,1926.5 2000,1910.5 2000,1810.73 1985.77,1796.5
GND on BOTTOM "BOTTOM-GND 3" (solid, remove dead copper, pour order 1202): 17 vertices, not listed, extent 2401,1353.52 2588,1416.5
5V_UNREG on BOTTOM "BOTTOM-5V_UNREG 1" (solid, remove dead copper, pour order 1205): 18 vertices, not listed, extent 1584.05,839.8 1711.12,1056
PMICOUT_3V3 on BOTTOM "BOTTOM-PMICOUT_3V3" (solid, remove dead copper, pour order 1209): 1462.22,1549 1520.6,1549 1540,1529.6 1540,1456.5 1484.04,1400.54 1368.25,1400.54 1368.25,1469.25 1396.57,1497.57 1396.57,1549
AR_1V8 on BOTTOM "BOTTOM-AR_1V8" (solid, remove dead copper, pour order 1198): 2424,1430.5 2424,1465.5 2434.98,1476.48 2526.78,1476.48 2527,1476.27 2527,1433.5 2453,1433.5 2450,1430.5 2424,1430.5
AR_VOUT_PA on BOTTOM "BOTTOM-AR_VOUT_PA" (solid, remove dead copper, pour order 1207): 2609,1264.5 2653,1264.5 2653,1185.5 2620,1152.5 2441,1152.5 2437,1156.5 2437,1200.5 2443,1206.5 2589,1206.5 2609,1226.5 2609,1264.5
MCU_5V on BOTTOM "BOTTOM-MCU_5V 1" (solid, remove dead copper, pour order 1208): 1783,347.5 1766,364.5 1766,475.5 1779,488.5 1824.86,488.5 1891,422.36 1891,356.5 1882,347.5 1783,347.5
MCU_5V on BOTTOM "BOTTOM-MCU_5V" (solid, remove dead copper, pour order 1210): 17 vertices, not listed, extent 415,464 584,597
5V_UNREG on BOTTOM "BOTTOM-5V_UNREG 2" (solid, remove dead copper, pour order 1203): 17 vertices, not listed, extent 1585,1105 1710.68,1313.16
PMIC_1V8 on BOTTOM "BOTTOM-PMIC_2V3 1" (solid, remove dead copper, pour order 1217): 18 vertices, not listed, extent 1560,593.4 1854.85,1029.4
5V_UNREG on BOTTOM "BOTTOM-5V_UNREG" (solid, remove dead copper, pour order 1204): 33 vertices, not listed, extent 1390.05,839.8 1518,1055.8
GND on BOTTOM "BOTTOM-GND 7" (solid, remove dead copper, pour order 1219): 375 vertices, not listed, extent 1574,144.5 1990.98,579
GND on BOTTOM "BOTTOM-GND" (solid, remove dead copper, pour order 1223): 2866.5,-131.45 2330.5,-131.45 2330.48,-131.48 2318.95,-131.48 2318.95,618.55 3047,618.55 3047,136 2916,136 2878,98 2871,91 2871,-131.45 2866.5,-131.45
AR_1V8 on BOTTOM "BOTTOM-AR_1V8 1" (solid, remove dead copper, pour order 1218): 462 vertices, not listed, extent 1980,956.11 2222,1554.5
AR_1P3_RF1 on BOTTOM "BOTTOM-AR_1P3_RF1" (solid, remove dead copper, pour order 1220): 109 vertices, not listed, extent 1709.24,1444.5 2686.52,1787.14
PMIC_1V0 on BOTTOM "GND 1-No Net" (solid, remove dead copper, pour order 1221): 36 vertices, not listed, extent 1198.58,621.88 1691.56,1866.4
MCU_5V on L3 "L3-MCU_5V" (solid, remove dead copper, pour order 1186): 17 vertices, not listed, extent 405,144.56 1866.22,592.98
GND on L3 "L3-GND 6" (solid, remove dead copper, pour order 1188): 722 vertices, not listed, extent -72.75,-132.5 3047.25,2372.5
AR_1V2 on L4 "L4-PMIC_1V2" (solid, remove dead copper, pour order 1189): 34 vertices, not listed, extent 1703.01,1411.5 2381.9,1819.48
5V_IN on L4 "L4-5V_IN" (solid, remove dead copper, pour order 1195): 471 vertices, not listed, extent 408.75,164.5 1597.98,2206.5
5V_UNREG on L4 "L4-5V_UNREG" (solid, remove dead copper, pour order 1193): 261 vertices, not listed, extent 1304.65,152.5 1795.2,1291.05
AR_1V8 on L4 "L4-AR_1V8" (solid, remove dead copper, pour order 1191): 509 vertices, not listed, extent 1942.47,848.07 2562,1589.5
GND on L4 "L4-GND" (solid, remove dead copper, pour order 1196): 722 vertices, not listed, extent -72.75,-132.5 3047.25,2372.5
GND on L2 "L2-GND 1" (solid, remove dead copper, pour order 1183): 2424.5,367 2424.5,120 2669.5,120 2669.5,367 2424.5,367
GND on L2 "L2-GND 2" (solid, remove dead copper, pour order 1184): 726 vertices, not listed, extent -72.74,-132.49 3047.24,2372.49
GND on L5 "L5-GND" (solid, remove dead copper, pour order 1197): 722 vertices, not listed, extent -72.75,-132.5 3047.25,2372.5

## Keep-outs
Keep-Out Layer:
  text ".Layer_Name" at -523,-1458.49 h60

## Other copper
TOP:
  region net PMIC_1V8: 2067.88,861.7 2067.88,835.2 2054.08,835.2 2054.08,861.7 2054.1,862.3 2054.18,862.9 2054.3,863.49 2054.48,864.06 2054.71,864.62 2054.98,865.16 2055.3,865.66 2055.67,866.14 2056.07,866.59 2056.51,867 2056.99,867.37 2057.5,867.7 2058.03,867.98 2058.58,868.21 2059.16,868.39 2059.74,868.53 2060.34,868.61 2060.94,868.64 2061.54,868.62 2062.14,868.54 2062.73,868.42 2063.3,868.24 2063.86,868.01 2064.4,867.74 2064.9,867.41 2065.38,867.05 2065.83,866.65 2066.24,866.21 2066.61,865.73 2066.94,865.22 2067.22,864.69 2067.45,864.14 2067.63,863.56 2067.77,862.98 2067.85,862.38 2067.88,861.78 2067.88,861.7
  region net PMIC_1V8: 2093.47,861.7 2093.47,835.2 2079.67,835.2 2079.67,861.7 2079.69,862.3 2079.77,862.9 2079.89,863.49 2080.07,864.06 2080.3,864.62 2080.57,865.16 2080.89,865.66 2081.26,866.14 2081.66,866.59 2082.1,867 2082.58,867.37 2083.09,867.7 2083.62,867.98 2084.17,868.21 2084.75,868.39 2085.33,868.53 2085.93,868.61 2086.53,868.64 2087.13,868.62 2087.73,868.54 2088.32,868.42 2088.89,868.24 2089.45,868.01 2089.99,867.74 2090.49,867.41 2090.97,867.05 2091.42,866.65 2091.83,866.21 2092.2,865.73 2092.53,865.22 2092.81,864.69 2093.04,864.14 2093.22,863.56 2093.36,862.98 2093.44,862.38 2093.47,861.78 2093.47,861.7
  region: 2108.38,2187.85 2108.38,2181.95 2120.19,2181.98 2143.83,2181.38 2291.61,2181.37 2315.22,2181.98 2327.03,2181.97 2327.03,2187.85 2315.22,2187.85 2291.61,2188.42 2143.81,2188.42 2120.18,2187.86 2108.38,2187.84
  region net NetR42_2: 1762.33,1967.48 1762.33,1943.88 1710.23,1943.88 1710.23,1967.48
  region net NetR39_2: 1762.33,2017.48 1762.33,1993.88 1710.23,1993.88 1710.23,2017.48
  region net AR_QSPI_CS: 1762.33,2067.48 1762.33,2043.88 1710.23,2043.88 1710.23,2067.48
  region net NetR44_1: 1980.23,1967.48 1980.23,1943.88 1928.13,1943.88 1928.13,1967.48
  region net NetR40_1: 1980.23,2017.48 1980.23,1993.88 1928.13,1993.88 1928.13,2017.48
  region net NetC1_2: 1980.23,2067.48 1980.23,2043.88 1928.13,2043.88 1928.13,2067.48
  region net NetR45_1: 1980.23,1917.48 1980.23,1893.88 1928.13,1893.88 1928.13,1917.48
  region net GND: 1762.33,1917.48 1762.33,1893.88 1710.23,1893.88 1710.23,1917.48
  pour cut-out: 1627.57,2279.9 1627.6,2266.09 1643.35,2266.09 1661.02,2262.72 2298.35,2262.72 2316.03,2266.1 2331.79,2266.11 2331.76,2279.89 2316.02,2279.86 2298.26,2283.24 1661.03,2283.24 1643.34,2279.88
  pour cut-out: 2104.44,2191.79 2104.45,2178 2120.19,2178.01 2137.73,2174.64 2297.74,2174.65 2315.27,2178.01 2330.97,2178 2330.96,2191.79 2315.2,2191.79 2297.71,2195.15 2137.7,2195.15 2120.2,2191.79
  region: 1631.53,2275.95 1631.54,2270.05 1643.36,2270.07 1666.96,2269.45 2223.49,2269.49 2292.4,2269.46 2316.03,2270.05 2327.83,2270.04 2327.83,2275.95 2316.02,2275.96 2292.39,2276.52 1666.97,2276.52 1643.36,2275.95
  text "1" at 76.39,102.36 h50
  text ".Layer_Name" at -523,-1458.49 h60
L2:
  pour cut-out: 2404.94,1324.36 2404.33,1327.43 2402.59,1330.04 2399.98,1331.78 2396.91,1332.39 2393.84,1331.78 2391.23,1330.04 2389.49,1327.43 2388.88,1324.36 2389.49,1321.29 2391.23,1318.68 2393.84,1316.94 2396.91,1316.33 2399.98,1316.94 2402.59,1318.68 2404.33,1321.29 2404.94,1324.36
  pour cut-out: 2353.76,1324.36 2353.15,1327.43 2351.41,1330.04 2348.8,1331.78 2345.73,1332.39 2342.66,1331.78 2340.05,1330.04 2338.31,1327.43 2337.7,1324.36 2338.31,1321.29 2340.05,1318.68 2342.66,1316.94 2345.73,1316.33 2348.8,1316.94 2351.41,1318.68 2353.15,1321.29 2353.76,1324.36
  pour cut-out: 2302.58,1324.36 2301.97,1327.43 2300.23,1330.04 2297.62,1331.78 2294.55,1332.39 2291.48,1331.78 2288.87,1330.04 2287.13,1327.43 2286.52,1324.36 2287.13,1321.29 2288.87,1318.68 2291.48,1316.94 2294.55,1316.33 2297.62,1316.94 2300.23,1318.68 2301.97,1321.29 2302.58,1324.36
  pour cut-out: 2456.12,1426.72 2455.51,1429.79 2453.77,1432.4 2451.16,1434.14 2448.09,1434.75 2445.02,1434.14 2442.41,1432.4 2440.67,1429.79 2440.06,1426.72 2440.67,1423.65 2442.41,1421.04 2445.02,1419.3 2448.09,1418.69 2451.16,1419.3 2453.77,1421.04 2455.51,1423.65 2456.12,1426.72
  pour cut-out: 2456.12,1477.9 2455.51,1480.97 2453.77,1483.58 2451.16,1485.32 2448.09,1485.93 2445.02,1485.32 2442.41,1483.58 2440.67,1480.97 2440.06,1477.9 2440.67,1474.83 2442.41,1472.22 2445.02,1470.48 2448.09,1469.87 2451.16,1470.48 2453.77,1472.22 2455.51,1474.83 2456.12,1477.9
  pour cut-out: 2456.12,1529.08 2455.51,1532.15 2453.77,1534.76 2451.16,1536.5 2448.09,1537.11 2445.02,1536.5 2442.41,1534.76 2440.67,1532.15 2440.06,1529.08 2440.67,1526.01 2442.41,1523.4 2445.02,1521.66 2448.09,1521.05 2451.16,1521.66 2453.77,1523.4 2455.51,1526.01 2456.12,1529.08
  pour cut-out: 2456.12,1580.26 2455.51,1583.33 2453.77,1585.94 2451.16,1587.68 2448.09,1588.29 2445.02,1587.68 2442.41,1585.94 2440.67,1583.33 2440.06,1580.26 2440.67,1577.19 2442.41,1574.58 2445.02,1572.84 2448.09,1572.23 2451.16,1572.84 2453.77,1574.58 2455.51,1577.19 2456.12,1580.26
  pour cut-out: 2456.12,1580.26 2455.51,1583.33 2453.77,1585.94 2451.16,1587.68 2448.09,1588.29 2445.02,1587.68 2442.41,1585.94 2440.67,1583.33 2440.06,1580.26 2440.67,1577.19 2442.41,1574.58 2445.02,1572.84 2448.09,1572.23 2451.16,1572.84 2453.77,1574.58 2455.51,1577.19 2456.12,1580.26
  pour cut-out: 2456.12,1529.08 2455.51,1532.15 2453.77,1534.76 2451.16,1536.5 2448.09,1537.11 2445.02,1536.5 2442.41,1534.76 2440.67,1532.15 2440.06,1529.08 2440.67,1526.01 2442.41,1523.4 2445.02,1521.66 2448.09,1521.05 2451.16,1521.66 2453.77,1523.4 2455.51,1526.01 2456.12,1529.08
  pour cut-out: 2456.12,1477.9 2455.51,1480.97 2453.77,1483.58 2451.16,1485.32 2448.09,1485.93 2445.02,1485.32 2442.41,1483.58 2440.67,1480.97 2440.06,1477.9 2440.67,1474.83 2442.41,1472.22 2445.02,1470.48 2448.09,1469.87 2451.16,1470.48 2453.77,1472.22 2455.51,1474.83 2456.12,1477.9
  pour cut-out: 2456.12,1426.72 2455.51,1429.79 2453.77,1432.4 2451.16,1434.14 2448.09,1434.75 2445.02,1434.14 2442.41,1432.4 2440.67,1429.79 2440.06,1426.72 2440.67,1423.65 2442.41,1421.04 2445.02,1419.3 2448.09,1418.69 2451.16,1419.3 2453.77,1421.04 2455.51,1423.65 2456.12,1426.72
  pour cut-out: 2302.58,1324.36 2301.97,1327.43 2300.23,1330.04 2297.62,1331.78 2294.55,1332.39 2291.48,1331.78 2288.87,1330.04 2287.13,1327.43 2286.52,1324.36 2287.13,1321.29 2288.87,1318.68 2291.48,1316.94 2294.55,1316.33 2297.62,1316.94 2300.23,1318.68 2301.97,1321.29 2302.58,1324.36
  pour cut-out: 2353.76,1324.36 2353.15,1327.43 2351.41,1330.04 2348.8,1331.78 2345.73,1332.39 2342.66,1331.78 2340.05,1330.04 2338.31,1327.43 2337.7,1324.36 2338.31,1321.29 2340.05,1318.68 2342.66,1316.94 2345.73,1316.33 2348.8,1316.94 2351.41,1318.68 2353.15,1321.29 2353.76,1324.36
  pour cut-out: 2404.94,1324.36 2404.33,1327.43 2402.59,1330.04 2399.98,1331.78 2396.91,1332.39 2393.84,1331.78 2391.23,1330.04 2389.49,1327.43 2388.88,1324.36 2389.49,1321.29 2391.23,1318.68 2393.84,1316.94 2396.91,1316.33 2399.98,1316.94 2402.59,1318.68 2404.33,1321.29 2404.94,1324.36
  pour cut-out: 2122.11,1431.86 2124.47,1431.86 2138.16,1445.55 2143.19,1445.55 2144.67,1447.02 2155.01,1447.02 2155.01,1439.3 2143.91,1439.3 2125.4,1420.79 2080.11,1420.79 2065.63,1406.3 2039.41,1406.3 2027.44,1394.33 2013.24,1394.33 1999.44,1408.13 1926.72,1408.13 1871.85,1353.26 1871.85,1230.53 1902.84,1199.54 1930.51,1199.54 1946.19,1183.86 1946.19,1149.26 1952.57,1142.88 2000.14,1142.88 2021.34,1164.08 2041.01,1164.08 2063.58,1186.65 2063.58,1257.29 2103.68,1297.39 2115.53,1285.54 2078.28,1248.3 2078.28,1181.19 2047.44,1150.35 2025.91,1150.35 2007.69,1132.12 1942.84,1132.12 1934.58,1140.38 1934.58,1175.55 1923.01,1187.12 1894.16,1187.12 1857.85,1223.43 1857.85,1359.22 1919.41,1420.79 2006.19,1420.79 2011.82,1426.43 2032.47,1426.43 2040.28,1418.61 2059.93,1418.61 2073.17,1431.86
  text "2" at 68.06,102.36 h50
  text ".Layer_Name" at -523,-1458.49 h60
